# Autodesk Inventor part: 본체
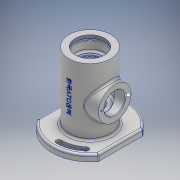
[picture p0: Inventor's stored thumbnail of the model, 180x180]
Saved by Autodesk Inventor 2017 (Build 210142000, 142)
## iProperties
Part Number: 본체
Material: 알루미늄 6061
Document SubType Name: Modeling
Designer: MRC
Density: 2.7 g/cm^3
Appearance: 알루미늄 - 평지
Mass: 687.093 g
Surface Area: 620.213 cm^2
Volume: 254.479 cm^3
Author: MRC
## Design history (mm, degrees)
sketch "스케치1"
  geometry: C1 r 32 at (0, 0); 1 further point
  constraints: 1 centre point, 1 coincident
  dimensions: "d0" = 64 diameter of C1
extrude "돌출1" new body sketch "스케치1" stored distance "d1" = 102; taper "d2" = 0 deg
sketch "스케치2"
  geometry: C1 r 58 at (0, 0); 1 further point
  constraints: 1 centre point, 1 coincident
  dimensions: "d3" = 116 diameter of C1
extrude "돌출2" join sketch "스케치2" distance "d4" = 10; taper "d5" = 0 deg
sketch "스케치4"
  geometry: L1 (47, -58)-(-47, -58); L2 (-47, -58)-(-47, 58); L3 (-47, 58)-(47, 58); L4 (47, 58)-(47, -58); L5 (47, -58)-(-47, 58); L6 (-47, -58)-(47, 58); L7 (-47, 58)-(-58.255, 58); L8 (-58.255, 58)-(-58.255, -58); L9 (-58.255, -58)-(-47, -58); L10 (47, -58)-(58.255, -58); L11 (58.255, -58)-(58.255, 58); L12 (58.255, 58)-(47, 58); 1 further point
  constraints: 24 end point, 4 perpendicular, 3 horizontal, 3 parallel, 2 midpoint
  dimensions: "d8" = 94 distance of L2.end L3.end; "d9" = 116 distance between parallel lines of L3 L1; "d10" = 11.25538 distance between parallel lines of L2 L8; "d11" = 11.255 distance between parallel lines of L4 L11
extrude "돌출3" cut sketch "스케치4" distance "d12" = 13; taper "d13" = 0 deg
sketch "스케치5"
  geometry: C1 r 36 at (0, 0); 1 further point
  constraints: 1 centre point, 1 coincident
  dimensions: "d14" = 72 diameter of C1
extrude "돌출4" join sketch "스케치5" distance "d15" = 3; taper "d16" = 0 deg
sketch "스케치6"
  geometry: C1 r 22.5 at (0, 0); 1 further point
  constraints: 1 centre point, 1 coincident
  dimensions: "d17" = 45 diameter of C1
extrude "돌출5" cut sketch "스케치6" distance "d18" = 8; taper "d19" = 0 deg
sketch "스케치7"
  geometry: C1 r 24 at (0, 0); 1 further point
  constraints: 1 centre point, 1 coincident
  dimensions: "d20" = 48 diameter of C1
extrude "돌출6" cut sketch "스케치7" distance "d21" = 3; taper "d22" = 0 deg
sketch "스케치9"
  geometry: C1 r 22.5 at (0, 0); 1 further point
  constraints: 1 centre point, 1 coincident
  dimensions: "d23" = 45 diameter of C1
extrude "돌출7" cut sketch "스케치9" distance "d24" = 22; taper "d25" = 0 deg
sketch "스케치10"
  geometry: C1 r 17.5 at (0, 0); 1 further point
  constraints: 1 centre point, 1 coincident
  dimensions: "d26" = 35 diameter of C1
extrude "돌출8" cut sketch "스케치10" distance "d27" = 4; taper "d28" = 0 deg
sketch "스케치12"
  geometry: C1 r 18.5 at (0, 0); 1 further point
  constraints: 1 centre point, 1 coincident
  dimensions: "d30" = 37 diameter of C1
extrude "돌출9" cut sketch "스케치12" distance "d31" = 1.75; taper "d32" = 0 deg
sketch "스케치13"
  geometry: C1 r 17.5 at (0, 0); 1 further point
  constraints: 1 centre point, 1 coincident
  dimensions: "d33" = 35 diameter of C1
extrude "돌출10" cut sketch "스케치13" distance "d34" = 11; taper "d35" = 0 deg
sketch "스케치14"
  geometry: C1 r 27 at (0, 0); 1 further point
  constraints: 1 centre point, 1 coincident
  dimensions: "d36" = 54 diameter of C1
extrude "돌출11" cut sketch "스케치14" distance "d37" = 38; taper "d38" = 0 deg
sketch "스케치15"
  geometry: C1 r 17.5 at (0, 0); 1 further point
  constraints: 1 centre point, 1 coincident
  dimensions: "d39" = 35 diameter of C1
extrude "돌출12" cut sketch "스케치15" distance "d40" = 11; taper "d41" = 0 deg
sketch "스케치16"
  geometry: C1 r 15 at (0, 0); 1 further point
  constraints: 1 centre point, 1 coincident
  dimensions: "d42" = 30 diameter of C1
extrude "돌출13" cut sketch "스케치16" distance "d43" = 5; taper "d44" = 0 deg
sketch "스케치17"
  geometry: C1 r 11 at (0, 0); 1 further point
  constraints: 1 centre point, 1 coincident
  dimensions: "d45" = 22 diameter of C1
extrude "돌출14" cut sketch "스케치17" distance "d46" = 30; taper "d47" = 0 deg
sketch "스케치18"
  geometry: L1 (36, -61)-(36, -64) reference; L2 (36, -64)-(11, -64) reference; L3 (11, -64)-(11, -40) reference; L4 (11, -40)-(15, -40) reference; L5 (15, -40)-(15, -35) reference; L6 (15, -35)-(17.5, -35) reference; L7 (17.5, -35)-(17.5, -24) reference; L8 (17.5, -24)-(27, -24) reference; L9 (27, -24)-(27, 14) reference; L10 (27, 14)-(17.5, 14) reference; L11 (17.5, 14)-(17.5, 25) reference; L12 (17.5, 25)-(18.5, 25) reference; L13 (18.5, 25)-(18.5, 26.75) reference; L14 (18.5, 26.75)-(17.5, 26.75) reference; L15 (17.5, 26.75)-(17.5, 29) reference; L16 (17.5, 29)-(22.5, 29) reference; L17 (22.5, 29)-(22.5, 43) reference; L18 (22.5, 43)-(24, 43) reference; L19 (24, 43)-(24, 46) reference; L20 (24, 46)-(22.5, 46) reference; L21 (22.5, 51)-(32, 51) reference; L22 (32, 51)-(32, -51) reference; L23 (32, -51)-(58, -51) reference; L24 (58, -51)-(58, -61) reference; L25 (58, -61)-(36, -61) reference; L26 (-58, -51)-(-32, -51) reference; L27 (-32, -51)-(-32, 51) reference; L28 (-32, 51)-(-22.5, 51) reference; L29 (-22.5, 46)-(-24, 46) reference; L30 (-24, 46)-(-24, 43) reference; L31 (-24, 43)-(-22.5, 43) reference; L32 (-22.5, 43)-(-22.5, 29) reference; L33 (-22.5, 29)-(-17.5, 29) reference; L34 (-17.5, 29)-(-17.5, 26.75) reference; L35 (-17.5, 26.75)-(-18.5, 26.75) reference; L36 (-18.5, 26.75)-(-18.5, 25) reference; L37 (-18.5, 25)-(-17.5, 25) reference; L38 (-17.5, 25)-(-17.5, 14) reference; L39 (-17.5, 14)-(-27, 14) reference; L40 (-27, 14)-(-27, -24) reference; L41 (-27, -24)-(-17.5, -24) reference; L42 (-17.5, -24)-(-17.5, -35) reference; L43 (-17.5, -35)-(-15, -35) reference; L44 (-15, -35)-(-15, -40) reference; L45 (-15, -40)-(-11, -40) reference; L46 (-11, -40)-(-11, -64) reference; L47 (-11, -64)-(-36, -64) reference; L48 (-36, -64)-(-36, -61) reference; L49 (-36, -61)-(-58, -61) reference; L50 (-58, -61)-(-58, -51) reference; L51 (-22.5, 51)-(22.5, 51) reference; L52 (0, 51)-(0, -64); L53 (-36, -64)-(36, -64) reference; L54 (0, -50)-(-20, -50); L55 (-20, -50)-(-30, -64); L56 (-15, -50)-(-15, -42.7); L57 (-15, -42.7)-(0, -42.7); L58 (22.5, 46)-(22.5, 51) reference; L59 (-22.5, 51)-(-22.5, 46) reference; 1 further point
  constraints: 10 end point, 4 point on line, 2 midpoint, 1 horizontal, 1 perpendicular, 1 vertical
  dimensions: "d49" = 40 diameter of L54.end L52; "d50" = 60 diameter of L55.end L52; "d51" = 14 distance between parallel lines of L53 L54; "d52" = 7.3 distance of L56.start L56.end; "d53" = 30 diameter of L56 L52
revolve "회전1" sketch "스케치18" stored, may be unused: angle "d54" = 90 deg
node "작업 평면1"
sketch "스케치20"
  geometry: L1 (32, 51)-(-32, 51) reference; C1 r 25 at (0, -5); 2 further points
  constraints: 1 centre point, 1 coincident, 1 midpoint, 1 vertical alignment
  dimensions: "d56" = 50 diameter of C1; "d134" = 56 distance from line of L1 point (0, -5)
extrude "돌출15" join sketch "스케치20" stored distance "d57" = 30; taper "d58" = 0 deg
sketch "스케치23"
  geometry: L1 (0, 0)-(30.854, -36.77); L2 (0, 0)-(0, -48); L3 (0, 0)-(-30.854, 36.77); L4 (0, 0)-(0, 48); C1 r 4 at (30.854, -36.77); A1 r 48 centre (0, 0) between (30.854, -36.77) and (0, -48); A2 r 48 centre (0, 0) between (0, -48) and (30.854, -36.77); A3 r 52 centre (0, 0) between (0, -52) and (33.425, -39.834); A4 r 44 centre (0, 0) between (0, -44) and (28.283, -33.706); A5 r 4 centre (0, -48) between (0, -44) and (0, -52); A6 r 4 centre (30.854, -36.77) between (33.425, -39.834) and (28.283, -33.706); A7 r 48 centre (0, 0) between (0, 48) and (-30.854, 36.77); A8 r 52 centre (0, 0) between (0, 52) and (-33.425, 39.834); A9 r 44 centre (0, 0) between (0, 44) and (-28.283, 33.706); A10 r 4 centre (0, 48) between (0, 44) and (0, 52); A11 r 4 centre (-30.854, 36.77) between (-33.425, 39.834) and (-28.283, 33.706); 1 further point
  constraints: 23 point on circle, 12 centre point, 8 end point, 8 tangent, 3 coincident, 1 collinear, 1 concentric, 1 vertical
  dimensions: "d71" = 96 diameter of A1; "d72" = 8 diameter of C1; "d73" = 40 deg angle of L2 L1; "d74" = 8 diameter of A5; "d77" = 8 diameter of A10; "d79" = 40 deg angle of L3 L4
extrude "돌출17" cut sketch "스케치23" distance "d75" = 4.4; taper "d76" = 0 deg
sketch "스케치24"
  geometry: L1 (47, 33.985)-(47, -33.985) reference; L2 (-47, -33.985)-(-47, 33.985) reference; C1 r 23.857 at (0, 0) reference; C2 r 4 at (-30.854, 36.77); C3 r 4 at (30.854, -36.77); A1 r 4 centre (-30.854, 36.77) between (-33.425, 39.834) and (-28.283, 33.706) reference; A2 r 44 centre (0, 0) between (0, 44) and (-28.283, 33.706) reference; A3 r 4 centre (0, 48) between (0, 44) and (0, 52) reference; A4 r 52 centre (0, 0) between (0, 52) and (-33.425, 39.834) reference; A5 r 4 centre (30.854, -36.77) between (33.425, -39.834) and (28.283, -33.706) reference; A6 r 44 centre (0, 0) between (0, -44) and (28.283, -33.706) reference; A7 r 4 centre (0, -48) between (0, -44) and (0, -52) reference; A8 r 52 centre (0, 0) between (0, -52) and (33.425, -39.834) reference; A9 r 58 centre (0, 0) between (-47, -33.985) and (47, -33.985) reference; A10 r 58 centre (0, 0) between (47, 33.985) and (-47, 33.985) reference; 1 further point
  constraints: 2 centre point, 2 coincident
  dimensions: "d80" = 8 diameter of C2; "d81" = 8 diameter of C3
extrude "돌출18" cut sketch "스케치24" stored distance "d82" = 4.4; taper "d83" = 0 deg
sketch "스케치25"
  geometry: L1 (47, 33.985)-(47, -33.985) reference; L2 (-47, -33.985)-(-47, 33.985) reference; C1 r 23.857 at (0, 0) reference; A1 r 4 centre (-30.854, 36.77) between (-28.283, 33.706) and (-33.425, 39.834) reference; A2 r 4 centre (-30.854, 36.77) between (-33.425, 39.834) and (-28.283, 33.706) reference; A3 r 44 centre (0, 0) between (0, 44) and (-28.283, 33.706) reference; A4 r 4 centre (0, 48) between (0, 44) and (0, 52) reference; A5 r 52 centre (0, 0) between (0, 52) and (-33.425, 39.834) reference; A6 r 4 centre (30.854, -36.77) between (28.283, -33.706) and (33.425, -39.834) reference; A7 r 4 centre (30.854, -36.77) between (33.425, -39.834) and (28.283, -33.706) reference; A8 r 44 centre (0, 0) between (0, -44) and (28.283, -33.706) reference; A9 r 4 centre (0, -48) between (0, -44) and (0, -52) reference; A10 r 52 centre (0, 0) between (0, -52) and (33.425, -39.834) reference; A11 r 58 centre (0, 0) between (-47, -33.985) and (47, -33.985) reference; A12 r 58 centre (0, 0) between (47, 33.985) and (-47, 33.985) reference; A13 r 48 centre (0, 0) between (0, 48) and (-30.854, 36.77); A14 r 50.25 centre (0, 0) between (0, 50.25) and (-32.3, 38.494); A15 r 45.75 centre (0, 0) between (0, 45.75) and (-29.408, 35.047); A16 r 2.25 centre (0, 48) between (0, 45.75) and (0, 50.25); A17 r 2.25 centre (-30.854, 36.77) between (-32.3, 38.494) and (-29.408, 35.047); A18 r 48 centre (0, 0) between (0, -48) and (30.854, -36.77); A19 r 50.25 centre (0, 0) between (0, -50.25) and (32.3, -38.494); A20 r 45.75 centre (0, 0) between (0, -45.75) and (29.408, -35.047); A21 r 2.25 centre (0, -48) between (0, -45.75) and (0, -50.25); A22 r 2.25 centre (30.854, -36.77) between (32.3, -38.494) and (29.408, -35.047); 1 further point
  constraints: 20 point on circle, 10 centre point, 8 tangent, 2 coincident
  dimensions: "d84" = 4.5 diameter of A16; "d85" = 4.5 diameter of A21
extrude "돌출19" cut sketch "스케치25" stored distance "d86" = 4.4; taper "d87" = 0 deg
sketch "스케치29"
  geometry: C1 r 25 at (0, 0); C2 r 25 at (0, 0) reference; 1 further point
  constraints: 2 coincident, 1 centre point
  dimensions: "d94" = 50 diameter of C1
extrude "돌출20" join sketch "스케치29" stored distance "d95" = 4.4; taper "d96" = 5 deg
feature "스레드1" dims "d109" = 8, "d110" = 0
fillet "모깎기1" dims "d111" = 3
chamfer "모따기1" distance "d112" = 1; stored, may be unused: second distance "d113" = 2, angle "d114" = 45 deg
chamfer "모따기2" distance "d115" = 1; stored, may be unused: second distance "d116" = 2, angle "d117" = 45 deg
fillet "모깎기2" dims "d118" = 3
chamfer "모따기3" distance "d119" = 1; stored, may be unused: second distance "d120" = 2, angle "d121" = 45 deg
fillet "모깎기3" dims "d122" = 0.6
fillet "모깎기4" dims "d123" = 3
fillet "모깎기5" dims "d124" = 0.5
chamfer "모따기4" distance "d125" = 0.7; stored, may be unused: second distance "d126" = 2, angle "d127" = 30 deg
fillet "모깎기6" dims "d128" = 3
node "작업 평면3"
sketch "스케치32"
  geometry: L1 (-47, -61)-(47, -61) reference; L2 (38, 20)-(38, -30) reference; 2 further points
  constraints: 1 vertical alignment, 1 other
  dimensions: "d130" = 62 distance from line of L1 point (0, 1)
feature "엠보싱1" sketch "스케치32" dims "d8" = 94, "d9" = 116, "d10" = 11.25538, "d11" = 11.255, "d132" = 0.5, "d133" = 0
sketch "스케치34"
  geometry: C1 r 25 at (0, 0) reference; C2 r 16 at (0, 0); 1 further point
  constraints: 1 centre point, 1 coincident
  dimensions: "d135" = 32 diameter of C2
extrude "돌출22" cut sketch "스케치34" stored distance "d136" = 4.4; taper "d137" = 0 deg
sketch "스케치35" dims "d138" = 41
  geometry: C1 r 25 at (0, 0) reference; 3 further points
  constraints: 2 vertical alignment, 1 coincident, 2 other
hole "구멍3" sketch "스케치35" at (0, 20.5) diameter "d139" = 2.459; stored, may be unused: countersink angle "d143" = 90 deg, drill point angle "d145" = 118 deg; dims "d140" = 6, "d141" = 4, "d142" = 2, "d144" = 8
chamfer "모따기5" distance "d147" = 1; stored, may be unused: second distance "d148" = 2, angle "d149" = 30 deg
fillet "모깎기7" dims "d150" = 3
fillet "모깎기8" dims "d151" = 3
fillet "모깎기9" dims "d152" = 3
node "솔리드1"
mirror "미러3"
node "절단 모서리 투영1"
node "절단 모서리 투영2"
node "절단 모서리 투영3"
other parameters: "d55" = 38, "d129" = -39, "d146" = 0
